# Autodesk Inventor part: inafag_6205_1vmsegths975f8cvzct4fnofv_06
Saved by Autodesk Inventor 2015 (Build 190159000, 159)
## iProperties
Company: TraceParts S.A.
Created: 2012-12
Part Number: inafag_6205_1vmsegths975f8cvzct4fnofv_06
Checked By: TraceParts S.A.
Catalog Web Link: www.traceparts.com
Document SubType Name: Modeling
Designer: TraceParts
Material: Generic
Density: 1 g/cm^3
Appearance: Default
Author: TraceParts
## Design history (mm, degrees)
feature "inafag_6205_1vmsegths975f8cvzct4fnofv"
body "Solid1"
